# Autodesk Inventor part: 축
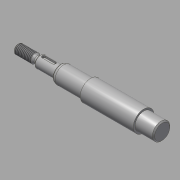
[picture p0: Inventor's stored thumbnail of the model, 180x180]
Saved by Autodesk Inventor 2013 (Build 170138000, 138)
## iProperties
Created: 2015-11
Part Number: 축
Material: 강철, 연강
Document SubType Name: Modeling
Designer: mduedu
Density: 7.86 g/cm^3
Mass: 167.296 g
Surface Area: 60.8056 cm^2
Volume: 21.2845 cm^3
Author: mduedu
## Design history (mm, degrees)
sketch "스케치1"
  geometry: L1 (-86, 0)-(86, 0); L2 (-86, 0)-(-86, 4); L3 (-86, 4)-(-70.732, 4); L4 (-70.732, 4)-(-69, 3); L5 (-69, 3)-(-67, 3); L6 (-67, 3)-(-67, 5); L7 (-67, 5)-(-49, 5); L8 (-49, 5)-(-49, 6.55); L9 (-47.355, 7.5)-(-23, 7.5); L10 (-23, 7.5)-(-23, 9); L11 (0, 0)-(0, 9); L12 (86, 4)-(70.732, 4); L13 (70.732, 4)-(69, 3); L14 (69, 3)-(67, 3); L15 (67, 3)-(67, 5); L16 (67, 5)-(49, 5); L17 (23, 7.5)-(23, 9); L18 (86, 0)-(86, 4); L19 (-23, 9)-(23, 9); L20 (-49, 6.55)-(-47.355, 7.5); L21 (47.355, 7.5)-(23, 7.5); L22 (49, 6.55)-(47.355, 7.5); L23 (49, 5)-(49, 6.55); 1 further point
  constraints: 46 end point, 10 symmetric about line, 6 perpendicular, 5 parallel, 2 midpoint, 1 coincident, 1 horizontal
  dimensions: "d0" = 172 distance of L1.start L1.end (derived); "d1" = 8 diameter of L3 L1; "d2" = 30 deg angle of L4 L5; "d3" = 6 diameter of L5 L1; "d4" = 10 diameter of L7 L1; "d5" = 15 diameter of L9 L1; "d6" = 18 diameter of L19 L1; "d8" = 18 distance of L6.end L7.end; "d9" = 46 distance of L10.end L17.end; "d10" = 2 distance of L4.end L5.end; "d11" = 17 distance from line of L4.end L2; "d16" = 13.1 diameter of L8.end L1; "d17" = 30 deg angle of L20 L9; "d18" = 26 distance between parallel lines of L10 L8
revolve "회전1" sketch "스케치1" stored, may be unused: angle "d12" = 90 deg
chamfer "모따기1" distance "d13" = 1; stored, may be unused: second distance "d14" = 2, angle "d15" = 45 deg
fillet "모깎기1" dims "d19" = 4, "d20" = 0.5
node "작업 평면1"
sketch "스케치2" dims "d23" = 12
  geometry: L1 (-5.5, 1.5)-(3.5, 1.5); L2 (3.5, 1.5)-(3.5, -1.5); L3 (3.5, -1.5)-(-5.5, -1.5); L4 (-5.5, -1.5)-(-5.5, 1.5); L5 (-9, -4)-(-9, 4) reference; 3 further points
  constraints: 8 end point, 2 midpoint, 2 parallel, 2 vertical alignment, 1 horizontal, 1 perpendicular, 4 other
  dimensions: "d21" = 3 distance between parallel lines of L3 L1; "d24" = 2 dimension on L5
extrude "돌출1" cut sketch "스케치2" distance "d25" = 1.8; taper "d26" = 0 deg
feature "스레드1" dims "d27" = 10, "d28" = 0
feature "스레드2" dims "d29" = 10, "d30" = 0
chamfer "모따기2" distance "d31" = 1; stored, may be unused: second distance "d32" = 2, angle "d33" = 45 deg
node "작업 평면2"
sketch "스케치3"
  geometry: C1 r 7.5 at (0, 0) reference; 1 further point
extrude "돌출2" cut sketch "스케치3" stored distance "d36" = 10; taper "d37" = 0 deg
chamfer "모따기3" distance "d38" = 1; stored, may be unused: second distance "d39" = 2, angle "d40" = 45 deg
node "솔리드1"
mirror "대칭1"
node "절단 모서리 투영1"
other parameters: "d35" = 16
